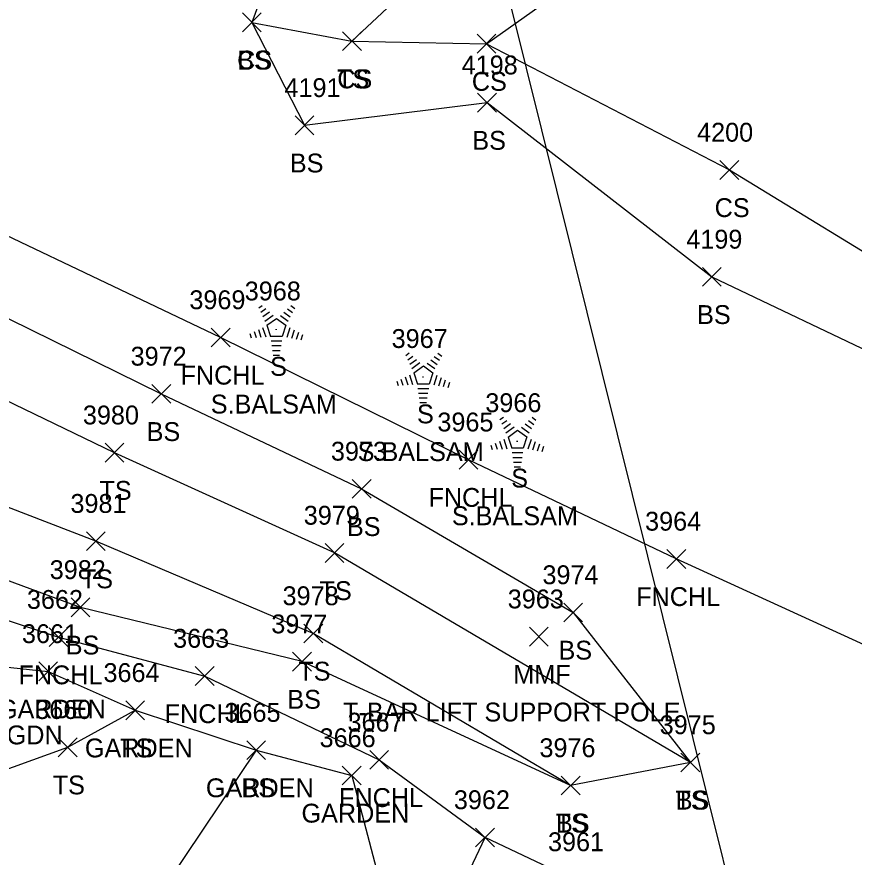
# Model space of a CAD drawing. Extents: x 49137 to 50946, y 9590 to 10709.
# Drawn here: x 49965.3 to 50054.1, y 10412.7 to 10501.9 of the extents above; entities that cross this region are included whole.
import ezdxf

# ---------------------------------------------------------------- set-up
doc = ezdxf.new("R2010")
doc.units = 0
for name, color, linetype in [('DCP', 7, 'Continuous'), ('L_A', 7, 'Continuous'), ('L_C', 7, 'Continuous'), ('L_I', 7, 'Continuous'), ('L_TIC', 7, 'Continuous'), ('LAPB', 7, 'Continuous'), ('LBC', 7, 'Continuous'), ('LELB', 7, 'Continuous'), ('LFNC', 7, 'Continuous'), ('LTC', 7, 'Continuous')]:
    doc.layers.add(name, color=color, linetype=linetype)

msp = doc.modelspace()

# ---------------------------------------------------------------- linework, layer by layer
at = {"layer": 'DCP'}
msp.add_lwpolyline([(50149.417, 9973.365), (49988.848, 10619.092)], dxfattribs=at)
at = {"layer": 'L_TIC'}
for points in [[(49989.199, 10500.293), (49991.199, 10502.293)], [(49991.199, 10500.293), (49989.199, 10502.293)], [(49989.199, 10500.293), (49991.199, 10502.293)], [(49991.199, 10500.293), (49989.199, 10502.293)], [(49999.826, 10498.298), (50001.826, 10500.298)], [(50001.826, 10498.298), (49999.826, 10500.298)], [(49999.826, 10498.298), (50001.826, 10500.298)], [(50001.826, 10498.298), (49999.826, 10500.298)], [(50014.103, 10498.037), (50016.103, 10500.037)], [(50016.103, 10498.037), (50014.103, 10500.037)], [(50014.103, 10498.037), (50016.103, 10500.037)], [(50016.103, 10498.037), (50014.103, 10500.037)], [(50014.157, 10491.779), (50016.157, 10493.779)], [(50016.157, 10491.779), (50014.157, 10493.779)], [(49994.79, 10489.374), (49996.79, 10491.374)], [(49996.79, 10489.374), (49994.79, 10491.374)], [(50039.871, 10484.639), (50041.871, 10486.639)], [(50041.871, 10484.639), (50039.871, 10486.639)], [(50038.005, 10473.292), (50040.005, 10475.292)], [(50040.005, 10473.292), (50038.005, 10475.292)], [(49985.887, 10466.864), (49987.887, 10468.864)], [(49987.887, 10466.864), (49985.887, 10468.864)], [(49979.594, 10460.877), (49981.594, 10462.877)], [(49981.594, 10460.877), (49979.594, 10462.877)], [(49974.62, 10454.638), (49976.62, 10456.638)], [(49976.62, 10454.638), (49974.62, 10456.638)], [(50012.195, 10453.894), (50014.195, 10455.894)], [(50014.195, 10453.894), (50012.195, 10455.894)], [(50000.85, 10450.797), (50002.85, 10452.797)], [(50002.85, 10450.797), (50000.85, 10452.797)], [(49972.642, 10445.251), (49974.642, 10447.251)], [(49974.642, 10445.251), (49972.642, 10447.251)], [(49997.977, 10444), (49999.977, 10446)], [(49999.977, 10444), (49997.977, 10446)], [(50034.236, 10443.367), (50036.236, 10445.367)], [(50036.236, 10443.367), (50034.236, 10445.367)], [(49971.01, 10438.228), (49973.01, 10440.228)], [(49973.01, 10438.228), (49971.01, 10440.228)], [(50023.298, 10437.685), (50025.298, 10439.685)], [(50025.298, 10437.685), (50023.298, 10439.685)], [(49995.719, 10435.455), (49997.719, 10437.455)], [(49997.719, 10435.455), (49995.719, 10437.455)], [(49968.685, 10435.066), (49970.685, 10437.066)], [(49970.685, 10435.066), (49968.685, 10437.066)], [(50019.661, 10435.12), (50021.661, 10437.12)], [(50021.661, 10435.12), (50019.661, 10437.12)], [(49994.525, 10432.469), (49996.525, 10434.469)], [(49996.525, 10432.469), (49994.525, 10434.469)], [(49967.592, 10431.435), (49969.592, 10433.435)], [(49969.592, 10431.435), (49967.592, 10433.435)], [(49984.2, 10430.942), (49986.2, 10432.942)], [(49986.2, 10430.942), (49984.2, 10432.942)], [(49976.813, 10427.307), (49978.813, 10429.307)], [(49978.813, 10427.307), (49976.813, 10429.307)], [(49976.813, 10427.307), (49978.813, 10429.307)], [(49978.813, 10427.307), (49976.813, 10429.307)], [(49969.66, 10423.384), (49971.66, 10425.384)], [(49971.66, 10423.384), (49969.66, 10425.384)], [(49989.651, 10423.08), (49991.651, 10425.08)], [(49991.651, 10423.08), (49989.651, 10425.08)], [(49989.651, 10423.08), (49991.651, 10425.08)], [(49991.651, 10423.08), (49989.651, 10425.08)], [(50002.706, 10422.046), (50004.706, 10424.046)], [(50004.706, 10422.046), (50002.706, 10424.046)], [(50002.706, 10422.046), (50004.706, 10424.046)], [(50004.706, 10422.046), (50002.706, 10424.046)], [(50035.739, 10421.77), (50037.739, 10423.77)], [(50037.739, 10421.77), (50035.739, 10423.77)], [(50035.739, 10421.77), (50037.739, 10423.77)], [(50037.739, 10421.77), (50035.739, 10423.77)], [(49999.797, 10420.39), (50001.797, 10422.39)], [(50001.797, 10420.39), (49999.797, 10422.39)], [(50023.032, 10419.332), (50025.032, 10421.332)], [(50025.032, 10419.332), (50023.032, 10421.332)], [(50023.032, 10419.332), (50025.032, 10421.332)], [(50025.032, 10419.332), (50023.032, 10421.332)], [(50013.946, 10413.815), (50015.946, 10415.815)], [(50015.946, 10413.815), (50013.946, 10415.815)], [(50013.946, 10413.815), (50015.946, 10415.815)], [(50015.946, 10413.815), (50013.946, 10415.815)], [(50013.946, 10413.815), (50015.946, 10415.815)], [(50015.946, 10413.815), (50013.946, 10415.815)]]:
    msp.add_lwpolyline(points, dxfattribs=at)
at = {"layer": 'LAPB'}
msp.add_lwpolyline([(49952.358, 10434.146), (49968.592, 10432.435), (49977.813, 10428.307), (49990.651, 10424.08), (50000.797, 10421.39), (50006.203, 10400.914), (50002.96, 10397.811), (50000.93, 10382.794), (49994.536, 10373.957), (49985.067, 10373.198), (49982.728, 10375.011), (49978.869, 10377.122), (49955.361, 10376.803), (49948.643, 10373.628)], dxfattribs=at)
at = {"layer": 'LBC'}
for points in [[(50008.97, 10402.171), (50018.577, 10397.777), (50024.366, 10410.355), (50014.946, 10414.815)], [(50008.97, 10402.171), (50014.946, 10414.815)]]:
    msp.add_lwpolyline(points, dxfattribs=at)
at = {"layer": 'LELB'}
for points in [[(49999.62, 10554.152), (49996.681, 10550.816), (49999.98, 10527.826), (49990.199, 10501.293), (50000.826, 10499.298), (50015.103, 10499.037), (50040.871, 10485.639), (50061.492, 10473.052)], [(50015.103, 10499.037), (50034.232, 10512.601), (50055.645, 10504.695), (50078.841, 10493.442), (50077.844, 10472.729), (50101.966, 10449.68), (50118.377, 10435.396), (50148.873, 10415.298)], [(50000.826, 10499.298), (50010.981, 10508.857)], [(49990.199, 10501.293), (49995.79, 10490.374), (50015.157, 10492.779), (50039.005, 10474.292), (50057.869, 10465.322), (50068.063, 10442.777), (50097.447, 10429.125), (50115.479, 10422.07), (50146.004, 10409.248), (50171.194, 10398.053), (50180.097, 10394.504), (50181.066, 10396.537)], [(49951.21, 10484.843), (49952.872, 10475.503), (49980.594, 10461.877), (50001.85, 10451.797), (50024.298, 10438.685), (50036.739, 10422.77), (50024.032, 10420.332), (49995.525, 10433.469), (49972.01, 10439.228), (49942.016, 10450.335), (49909.033, 10471.178)], [(50036.739, 10422.77), (49998.977, 10445), (49975.62, 10455.638), (49949.012, 10468.446), (49915.563, 10483.067)], [(50024.032, 10420.332), (49996.719, 10436.455), (49973.642, 10446.251), (49944.832, 10457.346), (49912.124, 10477.472)], [(49937.097, 10381.963), (49943.854, 10389.095), (49948.163, 10407.827), (49957.057, 10419.465), (49970.66, 10424.384), (49977.813, 10428.307)], [(49990.651, 10424.08), (49979.28, 10407.08), (49978.379, 10402.73)]]:
    msp.add_lwpolyline(points, dxfattribs=at)
at = {"layer": 'LFNC'}
for points in [[(50069.33, 10428.771), (50035.236, 10444.367), (50013.195, 10454.894), (49986.887, 10467.864), (49951.21, 10484.843), (49926.027, 10496.291)], [(49944.162, 10444.52), (49969.685, 10436.066), (49985.2, 10431.942), (50003.706, 10423.046)], [(50003.706, 10423.046), (50014.946, 10414.815)]]:
    msp.add_lwpolyline(points, dxfattribs=at)
at = {"layer": 'LTC'}
for p, q in [((49990.948, 10471.005), (49991.303, 10471.262)), ((49994.346, 10471.245), (49994.766, 10470.94)), ((49991.158, 10470.539), (49991.687, 10470.923)), ((49991.367, 10470.073), (49992.071, 10470.585)), ((49993.604, 10470.548), (49994.283, 10470.055)), ((49993.975, 10470.897), (49994.525, 10470.497)), ((49991.577, 10469.607), (49992.455, 10470.245)), ((49991.801, 10469.152), (49992.813, 10469.887)), ((49992.813, 10469.887), (49993.81, 10469.162)), ((49993.233, 10470.2), (49994.043, 10469.611)), ((49990.891, 10468.717), (49991.163, 10467.882)), ((49991.347, 10468.933), (49991.678, 10467.914)), ((49991.801, 10469.152), (49992.188, 10467.959)), ((49993.81, 10469.162), (49993.419, 10467.959)), ((49994.248, 10468.891), (49993.91, 10467.852)), ((49994.692, 10468.641), (49994.405, 10467.756)), ((49989.981, 10468.284), (49990.133, 10467.816)), ((49990.436, 10468.5), (49990.648, 10467.849)), ((49993.419, 10467.959), (49992.188, 10467.959)), ((49995.137, 10468.391), (49994.9, 10467.661)), ((49995.581, 10468.14), (49995.394, 10467.566)), ((49993.381, 10467.459), (49992.236, 10467.459)), ((49993.297, 10466.959), (49992.308, 10466.959)), ((49993.213, 10466.459), (49992.381, 10466.459)), ((49993.129, 10465.959), (49992.454, 10465.959)), ((50006.536, 10465.959), (50006.89, 10466.216)), ((50009.934, 10466.199), (50010.353, 10465.895)), ((50006.745, 10465.493), (50007.274, 10465.878)), ((50006.955, 10465.028), (50007.659, 10465.539)), ((50007.164, 10464.562), (50008.043, 10465.2)), ((50008.821, 10465.154), (50009.63, 10464.566)), ((50009.192, 10465.503), (50009.871, 10465.009)), ((50009.563, 10465.851), (50010.112, 10465.452)), ((50007.389, 10464.107), (50008.401, 10464.841)), ((50007.389, 10464.107), (50007.776, 10462.913)), ((50008.401, 10464.841), (50009.398, 10464.116)), ((50009.398, 10464.116), (50009.007, 10462.913)), ((50005.568, 10463.238), (50005.72, 10462.77)), ((50006.024, 10463.455), (50006.235, 10462.803)), ((50006.479, 10463.671), (50006.75, 10462.836)), ((50006.934, 10463.888), (50007.265, 10462.868)), ((50009.835, 10463.846), (50009.497, 10462.806)), ((50010.28, 10463.595), (50009.992, 10462.711)), ((50010.724, 10463.345), (50010.487, 10462.616)), ((50009.007, 10462.913), (50007.776, 10462.913)), ((50008.968, 10462.413), (50007.824, 10462.413)), ((50011.169, 10463.095), (50010.982, 10462.521)), ((50008.884, 10461.913), (50007.896, 10461.913)), ((50008.801, 10461.413), (50007.969, 10461.413)), ((50008.717, 10460.913), (50008.042, 10460.913)), ((50016.533, 10459.152), (50016.888, 10459.409)), ((50016.743, 10458.686), (50017.272, 10459.07)), ((50019.56, 10459.044), (50020.11, 10458.645)), ((50019.932, 10459.392), (50020.351, 10459.087)), ((50016.952, 10458.22), (50017.656, 10458.732)), ((50017.162, 10457.755), (50018.04, 10458.392)), ((50017.387, 10457.3), (50018.398, 10458.034)), ((50018.398, 10458.034), (50019.395, 10457.309)), ((50018.818, 10458.347), (50019.628, 10457.758)), ((50019.19, 10458.695), (50019.869, 10458.202)), ((50016.932, 10457.08), (50017.263, 10456.061)), ((50017.387, 10457.3), (50017.774, 10456.106)), ((50019.395, 10457.309), (50019.004, 10456.106)), ((50019.833, 10457.038), (50019.495, 10455.999)), ((50015.566, 10456.431), (50015.718, 10455.963)), ((50016.021, 10456.647), (50016.233, 10455.996)), ((50016.477, 10456.864), (50016.748, 10456.029)), ((50019.004, 10456.106), (50017.774, 10456.106)), ((50020.277, 10456.788), (50019.99, 10455.903)), ((50020.722, 10456.538), (50020.485, 10455.808)), ((50021.166, 10456.287), (50020.98, 10455.713)), ((50018.966, 10455.606), (50017.821, 10455.606)), ((50018.882, 10455.106), (50017.894, 10455.106)), ((50018.798, 10454.606), (50017.967, 10454.606)), ((50018.715, 10454.106), (50018.04, 10454.106))]:
    msp.add_line(p, q, dxfattribs=at)

# ---------------------------------------------------------------- texts
at = {"layer": 'L_A'}
for s, p in [('CS', (49988.64, 10496.293)), ('BS', (49988.64, 10496.293)), ('TS', (49999.235, 10494.298)), ('CS', (49999.267, 10494.298)), ('CS', (50013.544, 10494.037)), ('CS', (50013.544, 10494.037)), ('BS', (50013.598, 10487.779)), ('BS', (49994.231, 10485.374)), ('CS', (50039.312, 10480.639)), ('BS', (50037.446, 10469.292)), ('S', (49992.139, 10463.796)), ('FNCHL', (49982.635, 10462.864)), ('S', (50007.726, 10458.751)), ('BS', (49979.035, 10456.877)), ('S', (50017.724, 10451.943)), ('TS', (49974.029, 10450.638)), ('FNCHL', (50008.943, 10449.894)), ('BS', (50000.291, 10446.797)), ('TS', (49972.052, 10441.251)), ('TS', (49997.387, 10440)), ('FNCHL', (50030.984, 10439.367)), ('BS', (49970.451, 10434.228)), ('BS', (50022.739, 10433.685)), ('FNCHL', (49965.433, 10431.066)), ('TS', (49995.128, 10431.455)), ('MMF', (50017.945, 10431.12)), ('BS', (49993.966, 10428.469)), ('GARDEN', (49963.261, 10427.435)), ('FNCHL', (49980.948, 10426.942)), ('GARDEN', (49972.482, 10423.307)), ('TS', (49976.222, 10423.307)), ('TS', (49969.069, 10419.384)), ('GARDEN', (49985.321, 10419.08)), ('BS', (49989.092, 10419.08)), ('FNCHL', (49999.454, 10418.046)), ('FNCHL', (49999.454, 10418.046)), ('TS', (50035.148, 10417.77)), ('BS', (50035.18, 10417.77)), ('GARDEN', (49995.466, 10416.39)), ('TS', (50022.442, 10415.332)), ('BS', (50022.473, 10415.332))]:
    msp.add_text(s, height=2, dxfattribs=at).set_placement(p)
at = {"layer": 'L_C'}
for s, p in [('S.BALSAM', (49985.84, 10459.796)), ('S.BALSAM', (50001.427, 10454.751)), ('S.BALSAM', (50011.425, 10447.943)), ('T-BAR LIFT SUPPORT POLE', (49999.874, 10427.12)), ('MINI GOLF COURS INSIDE GDN', (49929.708, 10424.691))]:
    msp.add_text(s, height=2, dxfattribs=at).set_placement(p)
at = {"layer": 'L_I'}
for s, p in [('4198', (50012.464, 10495.779)), ('4191', (49993.664, 10493.374)), ('4200', (50037.446, 10488.639)), ('4199', (50036.304, 10477.292)), ('3968', (49989.446, 10471.796)), ('3969', (49983.572, 10470.864)), ('3967', (50005.034, 10466.751)), ('3972', (49977.334, 10464.877)), ('3966', (50014.976, 10459.943)), ('3980', (49972.273, 10458.638)), ('3965', (50009.888, 10457.894)), ('3973', (49998.59, 10454.797)), ('3981', (49970.949, 10449.251)), ('3979', (49995.71, 10448)), ('3964', (50031.929, 10447.367)), ('3982', (49968.75, 10442.228)), ('3974', (50021.038, 10441.685)), ('3662', (49966.331, 10439.066)), ('3978', (49993.459, 10439.455)), ('3963', (50017.354, 10439.12)), ('3977', (49992.266, 10436.469)), ('3661', (49965.804, 10435.435)), ('3663', (49981.846, 10434.942)), ('3664', (49974.458, 10431.307)), ('3664', (49974.458, 10431.307)), ('3660', (49967.219, 10427.384)), ('3665', (49987.297, 10427.08)), ('3665', (49987.297, 10427.08)), ('3667', (50000.351, 10426.046)), ('3667', (50000.351, 10426.046)), ('3975', (50033.479, 10425.77)), ('3975', (50033.479, 10425.77)), ('3666', (49997.388, 10424.39)), ('3976', (50020.718, 10423.332)), ('3976', (50020.718, 10423.332)), ('3962', (50011.639, 10417.815)), ('3962', (50011.639, 10417.815)), ('3962', (50011.639, 10417.815)), ('3961', (50021.626, 10413.355))]:
    msp.add_text(s, height=2, dxfattribs=at).set_placement(p)
at = {"layer": 'LTC'}
for p in [(49992.696, 10468.9), (50008.283, 10463.855), (50018.281, 10457.047)]:
    msp.add_text('.', height=1.037, rotation=270, dxfattribs=at).set_placement(p)

doc.saveas('drawing.dxf')
